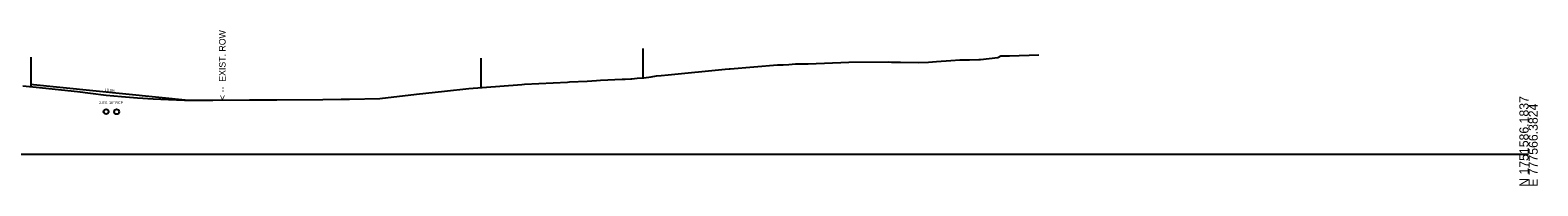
# Model space of a CAD drawing. Extents: x 776426 to 854588, y 1736205 to 1756790.
# Drawn here: x 806412.9 to 806873.6, y 1746705.1 to 1746752.6 of the extents above; entities that cross this region are included whole.
import ezdxf

# ---------------------------------------------------------------- set-up
doc = ezdxf.new("R2010")
doc.units = 0
for name, color, linetype in [('63', 7, 'Continuous'), ('DTM CONTOURS_MAJOR_TX', 7, 'Continuous'), ('DTM_X_FLOW_ARROWS', 7, 'Continuous'), ('TRANS_UNPAVED_SHOULDERS', 7, 'Continuous'), ('XS_P_DRIVEWAY', 7, 'Continuous'), ('XS_X_DRAINAGE', 7, 'Continuous'), ('XS_X_ROW', 7, 'Continuous'), ('XS_X_TX', 7, 'Continuous')]:
    doc.layers.add(name, color=color, linetype=linetype)

msp = doc.modelspace()

# ---------------------------------------------------------------- linework, layer by layer
at = {"layer": '63'}
msp.add_line((806413.14, 1746744.3), (806413.14, 1746735.3), dxfattribs=at)
msp.add_line((806413.14, 1746744.3), (806413.14, 1746735.3), dxfattribs=at)
at = {"layer": 'DTM CONTOURS_MAJOR_TX'}
msp.add_line((806370.79, 1746714.76), (806870.79, 1746714.76), dxfattribs=at)
at = {"layer": 'DTM_X_FLOW_ARROWS'}
msp.add_lwpolyline([(806410.65, 1746735.55), (806415.7, 1746735.04), (806420.5, 1746734.59), (806427.32, 1746733.81), (806431.38, 1746733.33), (806436.09, 1746732.77), (806440.84, 1746732.34), (806445.69, 1746731.96), (806450.45, 1746731.59), (806455.15, 1746731.42), (806460.07, 1746731.24), (806464.25, 1746731.25), (806468.76, 1746731.26), (806479.95, 1746731.27), (806488.28, 1746731.28), (806502.28, 1746731.42), (806507.9, 1746731.48), (806510.51, 1746731.52), (806519.71, 1746731.68), (806530.91, 1746733.06), (806539.51, 1746734.01), (806546.95, 1746734.74), (806550.98, 1746735.07), (806563.17, 1746736.04), (806563.93, 1746736.08), (806577.05, 1746736.73), (806577.74, 1746736.79), (806583.15, 1746737.03), (806585.98, 1746737.22), (806587.18, 1746737.29), (806593.8, 1746737.63), (806594.37, 1746737.65), (806594.77, 1746737.63), (806596.45, 1746737.7), (806596.79, 1746737.73), (806598.39, 1746737.89), (806600.46, 1746738.04), (806602.62, 1746738.31), (806604.26, 1746738.59), (806605.68, 1746738.72), (806607.88, 1746738.94), (806625.25, 1746740.67), (806626.5, 1746740.77), (806626.85, 1746740.8), (806641.31, 1746741.95), (806642.97, 1746742.03), (806644.75, 1746742.1), (806646.79, 1746742.3), (806650.29, 1746742.33), (806650.64, 1746742.34), (806663.06, 1746742.77), (806675.22, 1746742.88), (806676.09, 1746742.86), (806678.89, 1746742.84), (806684.28, 1746742.76), (806687.46, 1746742.84), (806689.89, 1746743.02), (806694.23, 1746743.3), (806697.03, 1746743.49), (806698.35, 1746743.5), (806699.97, 1746743.51), (806702.75, 1746743.63), (806703.33, 1746743.66), (806708.65, 1746744.28), (806709.57, 1746744.73), (806710.49, 1746744.7), (806711.62, 1746744.73), (806712.2, 1746744.75), (806721.13, 1746745.04)], dxfattribs=at)
at = {"layer": 'TRANS_UNPAVED_SHOULDERS'}
for p, q in [((806600.16, 1746747.02), (806600.16, 1746738.02)), ((806600.16, 1746747.02), (806600.16, 1746738.02)), ((806550.65, 1746744.04), (806550.65, 1746735.04)), ((806550.65, 1746744.04), (806550.65, 1746735.04))]:
    msp.add_line(p, q, dxfattribs=at)
at = {"layer": 'XS_P_DRIVEWAY'}
msp.add_line((806412.89, 1746736.09), (806461.33, 1746731.24), dxfattribs=at)
at = {"layer": 'XS_X_DRAINAGE'}
for centre in [(806436.1, 1746727.7), (806439.32, 1746727.68)]:
    msp.add_circle(centre, 0.75, dxfattribs=at)

# ---------------------------------------------------------------- texts
at = {"layer": 'DTM CONTOURS_MAJOR_TX'}
for s, p in [('N 1751586.1837', (806870.79, 1746704.76)), ('E 777566.3824', (806873.59, 1746704.76))]:
    msp.add_text(s, height=2.8, rotation=90, dxfattribs=at).set_placement(p)
at = {"layer": 'XS_P_DRIVEWAY'}
msp.add_text('10.0%', height=0.8, rotation=354.2894, dxfattribs=at).set_placement((806435.66, 1746734))
at = {"layer": 'XS_X_ROW'}
msp.add_text('< --  EXIST. ROW', height=2, rotation=90, dxfattribs=at).set_placement((806472.61, 1746731.26))
at = {"layer": 'XS_X_TX'}
msp.add_text('2-EX. 18" RCP', height=0.8, dxfattribs=at).set_placement((806433.93, 1746730.02))

doc.saveas('drawing.dxf')
